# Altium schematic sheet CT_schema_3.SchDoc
size 283 x 147 mm
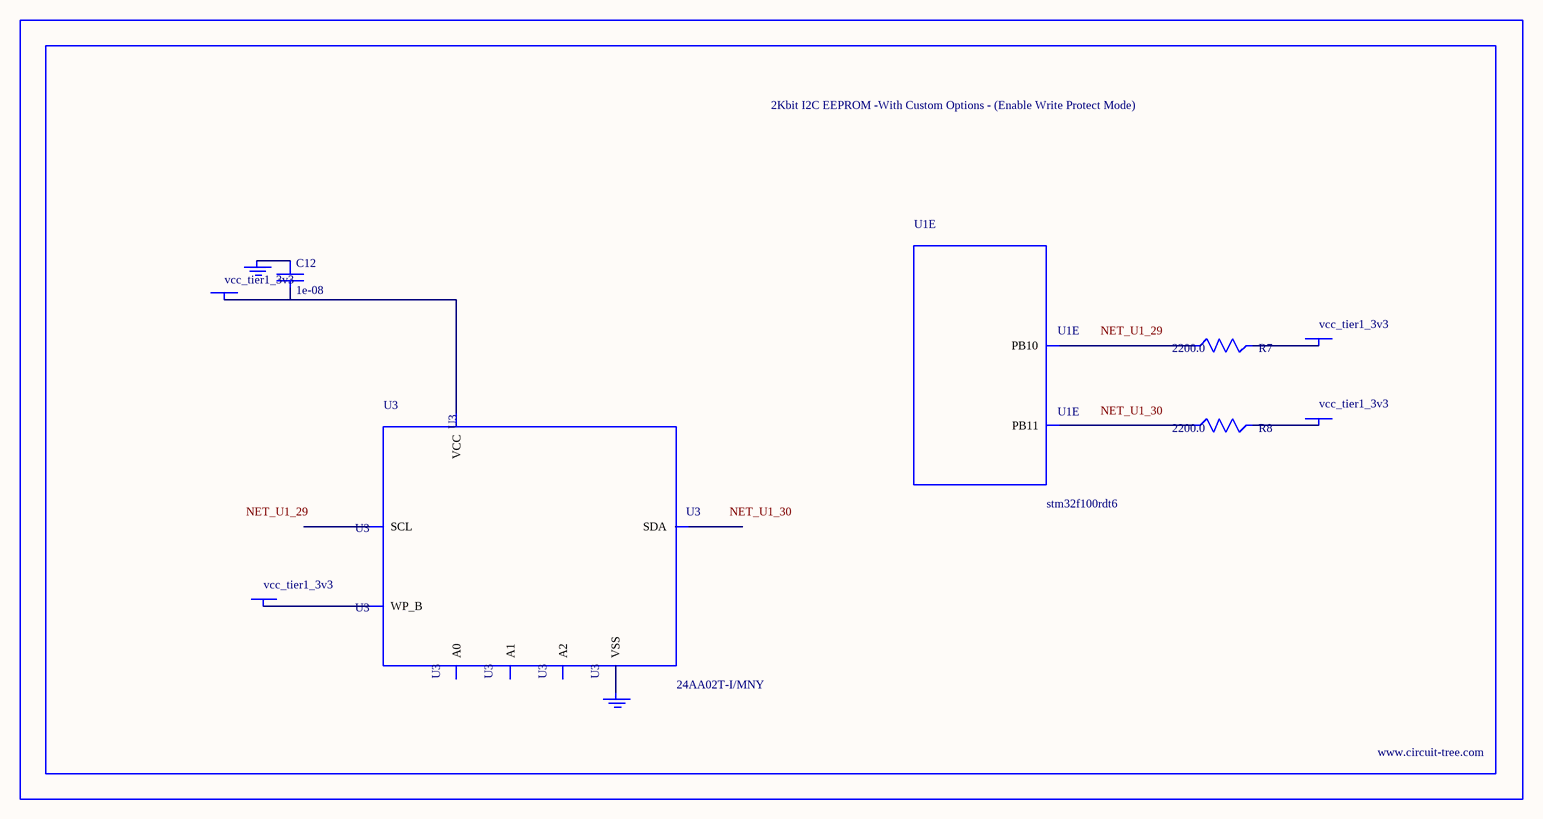
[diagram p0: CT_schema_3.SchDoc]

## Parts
BORDER2  (no value)
C12  1e-08  [C0402]
GND_INSTANCE_2_0  (no value)
GND_INSTANCE_2_1  (no value)
POWER_INSTANCE_2_0  vcc_tier1_3v3
POWER_INSTANCE_2_1  vcc_tier1_3v3
POWER_INSTANCE_2_2  vcc_tier1_3v3
POWER_INSTANCE_2_3  vcc_tier1_3v3
R7  2200.0  [R0603]
R8  2200.0  [R0603]
U1  stm32f100rdt6  [LQFP64]  (part E of 7)
U3  24AA02T-I/MNY  [TDFN-8/6MM]

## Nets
NetC12_1: C12.1 GND_INSTANCE_2_0.0(GND)
NetC12_2: C12.2 POWER_INSTANCE_2_1.0(PWR) U3.8(VCC)
NetGND_INSTANCE_2_1_0: GND_INSTANCE_2_1.0(GND) U3.4(VSS)
NetPOWER_INSTANCE_2_0_0: POWER_INSTANCE_2_0.0(PWR) U3.7(WP_B)
NetPOWER_INSTANCE_2_2_0: POWER_INSTANCE_2_2.0(PWR) R7.2
NetPOWER_INSTANCE_2_3_0: POWER_INSTANCE_2_3.0(PWR) R8.2
NetR7_1: R7.1 U1.29(PB10)
NetR8_1: R8.1 U1.30(PB11)

Not connected (* = marked no-connect by the designer): U3 1(A0) 2(A1) 3(A2) 5(SDA) 6(SCL)

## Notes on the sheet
- Labels drawn without touching a wire or pin: NET_U1_29, NET_U1_30

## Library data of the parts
BORDER2 = BORDER_PAGE2
C12 = C0402C103K3RAC
GND_INSTANCE_2_0 GND_INSTANCE_2_1 = GND
POWER_INSTANCE_2_0-POWER_INSTANCE_2_3 = PWR
R7 R8 = RC0603JR-072K2L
